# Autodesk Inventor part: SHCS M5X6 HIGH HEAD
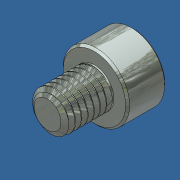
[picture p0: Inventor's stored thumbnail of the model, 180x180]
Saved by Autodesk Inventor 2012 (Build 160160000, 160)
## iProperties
Created: 2014-05
Part Number: SHCS M5X6 HIGH HEAD
Material: Steel
Document SubType Name: Modeling
Designer: Admin
Density: 7.85 g/cm^3
Mass: 2.62952 g
Surface Area: 4.15143 cm^2
Volume: 0.33497 cm^3
Translation Standard: STEP AP203
FileName: 91290A221.step
PreProcessor: SolidWorks 2010
PostProcessor: Build: 160, Release: 2012 RTM - Date: Tue 03/01/2011
Sent Units: inch
Uncertainty: 1e-05
Author: Admin
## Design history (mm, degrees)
node "91290A2211"
node "Base1"
body "Solid1"
